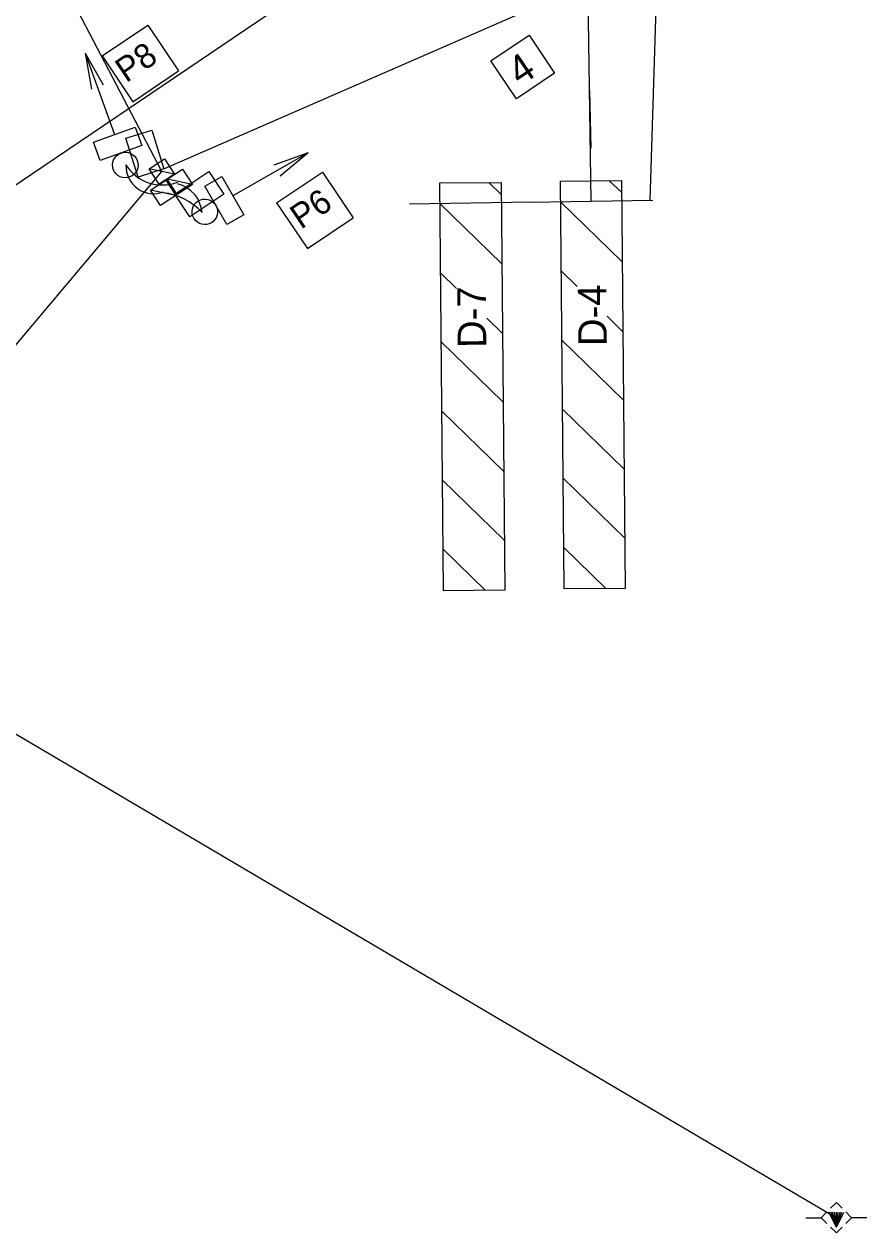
# Model space of a CAD drawing. Extents: x 509004 to 509991, y 882089 to 882397.
# Drawn here: x 509136.6 to 509219.3, y 882119.2 to 882237.8 of the extents above; entities that cross this region are included whole.
import ezdxf

# ---------------------------------------------------------------- set-up
doc = ezdxf.new("R2010")
doc.units = 0
for name, color, linetype in [('ConstLines', 7, 'Continuous'), ('Default', 7, 'Continuous'), ('TextAlgnCardinalPnt', 7, 'Continuous'), ('TextAlgnCurveData', 7, 'Continuous'), ('TextAlgnStation100', 7, 'Continuous'), ('TextAlgnStation1000', 7, 'Continuous'), ('TextAlgnStation500', 7, 'Continuous'), ('TextAlgnTangent', 7, 'Continuous'), ('TextAlgnTicks1000', 7, 'Continuous'), ('TextAlgnTicks500', 7, 'Continuous')]:
    doc.layers.add(name, color=color, linetype=linetype)

msp = doc.modelspace()

# ---------------------------------------------------------------- linework, layer by layer
at = {"layer": 'ConstLines'}
for p, q in [((509192.24, 882220.42), (509190.2, 882353.18)), ((509198.03, 882220.51), (509200.14, 882290.82)), ((509192.07, 882231.28), (509192.2, 882225.63)), ((509186.41, 882220.33), (509174.43, 882220.15)), ((509186.2, 882220.33), (509198.28, 882220.52))]:
    msp.add_line(p, q, dxfattribs=at)
at = {"layer": 'Default'}
msp.add_line((509133.54, 882220.5), (509164.96, 882241.77), dxfattribs=at)
at = {"layer": 'TextAlgnCardinalPnt'}
for p, q in [((509150.12, 882223.33), (509108.95, 882302.45)), ((509150.34, 882223.59), (509205.76, 882247.8)), ((509114.21, 882180.66), (509150.12, 882223.33))]:
    msp.add_line(p, q, dxfattribs=at)
at = {"layer": 'TextAlgnCurveData'}
for centre, radius, start, end in [((509150.17, 882226.21), 4.19, 212.0113, 290.7799), ((509149.34, 882223.89), 2.73, 177.8447, 290.7218), ((509149.54, 882215.11), 6.19, 42.7787, 83.263), ((509150.94, 882219.07), 3.14, 4.4062, 76.6687)]:
    msp.add_arc(centre, radius, start, end, dxfattribs=at)
at = {"layer": 'TextAlgnStation100'}
for p, q in [((509148.88, 882223.59), (509150.38, 882224.57)), ((509150.38, 882224.57), (509151.37, 882223.07)), ((509149.87, 882222.09), (509148.88, 882223.59)), ((509151.37, 882223.07), (509148.88, 882223.59)), ((509150.66, 882222.58), (509152.15, 882223.56)), ((509152.15, 882223.56), (509153.14, 882222.07)), ((509149.02, 882221.51), (509150.52, 882222.49)), ((509151.37, 882223.07), (509149.87, 882222.09)), ((509150.52, 882222.49), (509151.5, 882220.99)), ((509151.64, 882221.08), (509150.66, 882222.58)), ((509153.14, 882222.07), (509150.66, 882222.58)), ((509150, 882220.01), (509149.02, 882221.51)), ((509151.5, 882220.99), (509149.02, 882221.51)), ((509153.14, 882222.07), (509151.64, 882221.08)), ((509151.5, 882220.99), (509150, 882220.01))]:
    msp.add_line(p, q, dxfattribs=at)
at = {"layer": 'TextAlgnStation1000'}
msp.add_lwpolyline([(509188.65, 882233), (509184.9, 882230.48), (509182.4, 882234.2), (509186.15, 882236.72)], close=True, dxfattribs=at)
at = {"layer": 'TextAlgnStation500'}
for p, q in [((509144.27, 882234.67), (509148.75, 882237.69)), ((509148.75, 882237.69), (509151.76, 882233.21)), ((509142.61, 882234.96), (509145.48, 882226.96)), ((509142.61, 882234.96), (509144.39, 882231.85)), ((509142.61, 882234.96), (509143.22, 882231.43)), ((509144.27, 882234.67), (509147.28, 882230.19)), ((509147.28, 882230.19), (509151.76, 882233.21)), ((509164.47, 882225.18), (509157.1, 882220.96)), ((509164.47, 882225.18), (509161.1, 882223.97)), ((509164.47, 882225.18), (509161.72, 882222.89)), ((509161.39, 882220.28), (509165.87, 882223.29)), ((509165.87, 882223.29), (509168.88, 882218.81)), ((509161.39, 882220.28), (509164.4, 882215.8)), ((509164.4, 882215.8), (509168.88, 882218.81))]:
    msp.add_line(p, q, dxfattribs=at)
at = {"layer": 'TextAlgnTangent'}
for p, q in [((509213.28, 882120.73), (509214.78, 882120.73)), ((509214.78, 882120.73), (509215.35, 882121.3)), ((509215.35, 882120.17), (509214.78, 882120.73)), ((509216.27, 882119.79), (509215.52, 882121.28)), ((509216.27, 882119.79), (509215.72, 882121.28)), ((509216.27, 882119.79), (509215.89, 882121.28)), ((509216.27, 882119.79), (509216.09, 882121.28)), ((509216.27, 882119.79), (509217.02, 882121.28)), ((509216.27, 882119.79), (509216.63, 882121.28)), ((509216.27, 882119.79), (509216.81, 882121.28)), ((509216.27, 882119.79), (509216.45, 882121.28)), ((509216.27, 882119.79), (509216.27, 882121.28)), ((509216.27, 882120.73), (509216.27, 882120.73)), ((509219.26, 882120.73), (509217.76, 882120.73))]:
    msp.add_line(p, q, dxfattribs=at)
for points in [[(509215.7, 882121.65), (509216.27, 882122.22), (509216.84, 882121.65)], [(509217.19, 882121.3), (509217.76, 882120.73), (509217.19, 882120.17)], [(509216.84, 882119.81), (509216.27, 882119.25), (509215.7, 882119.81)]]:
    msp.add_lwpolyline(points, dxfattribs=at)
at = {"layer": 'TextAlgnTicks1000'}
for p, q in [((509177.39, 882222.22), (509183.39, 882222.27)), ((509177.75, 882182.22), (509177.39, 882222.22)), ((509183.4, 882221.1), (509182.18, 882222.26)), ((509183.39, 882222.27), (509183.75, 882182.27)), ((509189.21, 882222.4), (509195.21, 882222.45)), ((509189.57, 882182.4), (509189.21, 882222.4)), ((509195.22, 882221.28), (509194, 882222.44)), ((509195.21, 882222.45), (509195.57, 882182.45)), ((509183.46, 882214.29), (509177.4, 882220.19)), ((509195.28, 882214.47), (509189.23, 882220.37)), ((509179.04, 882211.87), (509177.47, 882213.41)), ((509190.86, 882212.05), (509189.29, 882213.59)), ((509181.99, 882208.97), (509183.52, 882207.45)), ((509193.81, 882209.15), (509195.34, 882207.63)), ((509189.35, 882206.81), (509195.4, 882200.92)), ((509177.53, 882206.63), (509183.58, 882200.74)), ((509177.59, 882199.85), (509183.64, 882193.96)), ((509189.41, 882200.03), (509195.46, 882194.14)), ((509177.65, 882193.07), (509183.7, 882187.18)), ((509189.47, 882193.25), (509195.52, 882187.37)), ((509177.71, 882186.29), (509181.86, 882182.25)), ((509189.53, 882186.48), (509193.68, 882182.43)), ((509183.75, 882182.27), (509177.75, 882182.22)), ((509195.57, 882182.45), (509189.57, 882182.4)), ((509125.57, 882174.22), (509216.27, 882120.73))]:
    msp.add_line(p, q, dxfattribs=at)
at = {"layer": 'TextAlgnTicks500'}
for p, q in [((509143.44, 882226.22), (509147.53, 882227.69)), ((509147.53, 882227.69), (509148.17, 882225.89)), ((509144.09, 882224.43), (509143.44, 882226.22)), ((509148.17, 882225.89), (509144.09, 882224.43)), ((509154.36, 882221.9), (509156.02, 882222.84)), ((509156.02, 882222.84), (509158.17, 882219.08)), ((509156.52, 882218.13), (509154.36, 882221.9)), ((509158.17, 882219.08), (509156.52, 882218.13))]:
    msp.add_line(p, q, dxfattribs=at)
for points in [[(509149.15, 882227.41), (509150.34, 882223.59), (509147.8, 882222.79), (509146.61, 882226.61)], [(509156.21, 882221.11), (509152.88, 882218.9), (509151.41, 882221.12), (509154.74, 882223.34)]]:
    msp.add_lwpolyline(points, close=True, dxfattribs=at)
for centre, major_axis in [((509146.55, 882223.98), (-1.06, -0.67)), ((509154.35, 882219.39), (-0.844, 0.922))]:
    msp.add_ellipse(centre, major_axis=major_axis, ratio=0.999996, dxfattribs=at)

# ---------------------------------------------------------------- texts
at = {"layer": 'TextAlgnStation1000'}
msp.add_text('4', height=2.8, rotation=33.9138, dxfattribs=at).set_placement((509185.27, 882231.68))
at = {"layer": 'TextAlgnStation500'}
for s, p in [('P8', (509146.63, 882231.99)), ('P6', (509163.77, 882217.62))]:
    msp.add_text(s, height=2.399, rotation=33.9138, dxfattribs=at).set_placement(p)
at = {"layer": 'TextAlgnTangent'}
for s, p in [('D-7', (509181.95, 882206.05)), ('D-4', (509193.77, 882206.23))]:
    msp.add_text(s, height=2.8, rotation=90.515, dxfattribs=at).set_placement(p)

doc.saveas('drawing.dxf')
